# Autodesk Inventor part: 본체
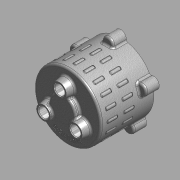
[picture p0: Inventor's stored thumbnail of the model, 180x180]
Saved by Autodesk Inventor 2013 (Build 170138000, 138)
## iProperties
Created: 2015-11
Part Number: 본체
Document SubType Name: 모델링
Designer: mdu
Material: 알루미늄 6061
Density: 2.71 g/cm^3
Mass: 487.651 g
Surface Area: 696.798 cm^2
Volume: 179.945 cm^3
변환 표준: STEP AP214IS
파일 이름: C:\Users\SeoGD\Desktop\?쒗뿕\紐몄껜.stp
전처리기: Build: 253, Release: 2010 SP1 - Date: Wed 07/29/2009
전송 단위: 밀리미터
불확실성: 0.01
Author: mdu
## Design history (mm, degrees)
sketch "스케치2"
  geometry: C1 r 50 at (0, 0); 1 further point
  constraints: 1 centre point, 1 coincident
  dimensions: "d9" = 100 diameter of C1
extrude "돌출2" new body sketch "스케치2" distance "d10" = 80; taper "d11" = 0 deg
feature "쉘1" dims "d12" = 5
sketch "스케치3" dims "d13" = 55
  geometry: C1 r 7.5 at (0, 27.5); C2 r 12.5 at (0, 27.5); 2 further points
  constraints: 2 centre point, 2 coincident, 2 vertical alignment, 2 other
  dimensions: "d14" = 15 diameter of C1; "d15" = 25 diameter of C2
extrude "돌출3" join sketch "스케치3" distance "d16" = 12; taper "d17" = -10 deg
hole "구멍2" diameter "d20" = 15; stored, may be unused: countersink angle "d24" = 90 deg, drill point angle "d26" = 118 deg; dims "d18" = 10, "d19" = 10, "d21" = 6, "d22" = 4, "d23" = 2, "d25" = 15
chamfer "모따기1" distance "d27" = 1; stored, may be unused: second distance "d28" = 2, angle "d29" = 45 deg
sketch "스케치4"
  geometry: L1 (0, 0)-(0, 88); L2 (0, 70)-(13.16, 70); L3 (-45, 75)-(45, 75) reference; L4 (-50, 80)-(50, 80) reference; L5 (13.16, 70)-(14.5, 75); L6 (20, 80)-(20, 88); L7 (20, 88)-(0, 88); L8 (20, 80)-(14.5, 75)
  constraints: 12 end point, 3 point on line, 2 perpendicular, 1 vertical
  dimensions: "d34" = 40 diameter of L6 L1; "d35" = 105 deg angle of L5 L3; "d36" = 5 distance between parallel lines of L2 L3; "d37" = 8 distance between parallel lines of L7 L4; "d51" = 29 diameter of L5.end L1
revolve "회전1" sketch "스케치4" stored, may be unused: angle "d38" = 90 deg
hole "구멍3" diameter "d41" = 15; stored, may be unused: countersink angle "d45" = 90 deg, drill point angle "d47" = 0 deg; dims "d39" = 10, "d40" = 10, "d42" = 6, "d43" = 22, "d44" = 13, "d46" = 15
chamfer "모따기2" distance "d48" = 1; stored, may be unused: second distance "d49" = 2, angle "d50" = 45 deg
fillet "모깎기1" dims "d52" = 3
fillet "모깎기2" dims "d53" = 3, "d72" = 0.2
sketch "스케치5"
  geometry: A1 r 50 centre (0, 0) between (50, 0) and (-8.074, 49.344) reference; A2 r 8.5 centre (0, 52) between (8.074, 49.344) and (-8.074, 49.344); 1 further point
  constraints: 5 point on circle, 1 centre point, 1 horizontal alignment
  dimensions: "d54" = 90 deg dimension on point (0, 0) A2.centre A1.start; "d55" = 52 distance of A2.centre point (0, 0); "d56" = 17 diameter of A2
extrude "돌출4" join sketch "스케치5" distance "d57" = 20; taper "d58" = 0 deg
fillet "모깎기3" dims "d59" = 3
hole "구멍4" diameter "d62" = 4.134; stored, may be unused: countersink angle "d66" = 90 deg, drill point angle "d68" = 118 deg; dims "d60" = 10, "d61" = 10, "d63" = 12, "d64" = 22, "d65" = 13, "d67" = 15
sketch "스케치6"
  geometry: C1 r 47 at (0, 0) reference; C2 r 42.5 at (0, 0); 1 further point
  constraints: 1 centre point, 1 coincident, 1 other
  dimensions: "d73" = 85 diameter of C2
feature "엠보싱1" sketch "스케치6" dims "d74" = 0.5, "d75" = 0
node "작업 평면1"
sketch "스케치7"
  geometry: A1 r 50 centre (0, 0) between (5.144, 49.735) and (-5.144, 49.735) reference; A2 r 3 centre (0, 47.916) between (2.204, 49.951) and (-2.204, 49.951); 1 further point
  constraints: 4 point on circle, 1 centre point, 1 vertical alignment
  dimensions: "d77" = 3 radius of A2
extrude "돌출5" join sketch "스케치7" distance "d79" = 15; taper "d80" = 0 deg
fillet "모깎기4" dims "d81" = 1
fillet "모깎기5" dims "d82" = 1
node "솔리드1"
node "솔리드 본체"
node "곡면 본체"
pattern_circular "원형 패턴1" dims "d31" = 360 deg
pattern_circular "원형 패턴2" dims "d70" = 360 deg
pattern_circular "원형 패턴3" dims "d84" = 360 deg
pattern_linear "직사각형 패턴1" dims "d89" = 25
node "솔리드2"
